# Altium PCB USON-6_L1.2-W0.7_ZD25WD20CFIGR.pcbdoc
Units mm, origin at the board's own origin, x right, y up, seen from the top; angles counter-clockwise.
Board outline 13.75 x 14.1 mm, 2 copper layers (Top Layer, Bottom Layer), stack 0 mm thick; 1 components, 0 nets, 6 pads, 0 vias.
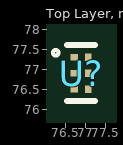
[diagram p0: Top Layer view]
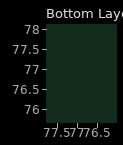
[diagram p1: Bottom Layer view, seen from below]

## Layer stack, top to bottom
Top Layer: signal copper (thickness not stored)
Bottom Layer: signal copper (thickness not stored)

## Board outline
83.603,69.85 69.85,69.85 69.85,83.95 83.603,83.95

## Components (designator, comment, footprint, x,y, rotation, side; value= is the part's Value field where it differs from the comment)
U? "" USON-6_L1.2-W0.7_ZD25WD20CFIGR 76.903,76.9 r0 top

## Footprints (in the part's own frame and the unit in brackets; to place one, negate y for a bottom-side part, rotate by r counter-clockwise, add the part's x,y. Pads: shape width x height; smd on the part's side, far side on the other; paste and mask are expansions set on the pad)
USON-6_L1.2-W0.7_ZD25WD20CFIGR [mm]
  rect 0.18x0.16 smd paste+0 mask+0.05: 1(-0.175,0.4) 2(-0.175,0) 3(-0.175,-0.4)
  rect 0.16x0.18 smd paste+0 mask+0.05: 4(0.175,-0.4) 5(0.175,0) 6(0.175,0.4)
  silkscreen extent -0.7,-0.7 0.35,0.7

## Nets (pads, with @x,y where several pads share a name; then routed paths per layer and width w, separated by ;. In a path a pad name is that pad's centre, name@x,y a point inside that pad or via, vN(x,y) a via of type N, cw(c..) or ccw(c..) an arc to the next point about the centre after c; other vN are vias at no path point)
pads on no net: U?.1 U?.2 U?.3 U?.4 U?.5 U?.6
